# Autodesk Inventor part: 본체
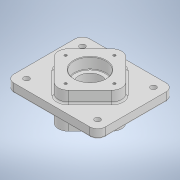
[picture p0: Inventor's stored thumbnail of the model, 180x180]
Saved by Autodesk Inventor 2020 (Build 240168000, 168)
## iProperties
Created: 2021-07
Part Number: 본체
Material: 일반
Document SubType Name: Modeling
Designer: Owner
Density: 1 g/cm^3
Appearance: 기본값
Mass: 807.973 g
Surface Area: 961.691 cm^2
Volume: 807.973 cm^3
Author: Owner
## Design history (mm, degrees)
sketch "스케치1"
  geometry: L1 (-90, 75)-(90, 75); L2 (90, 75)-(90, -75); L3 (90, -75)-(-90, -75); L4 (-90, -75)-(-90, 75); L5 (-90, 75)-(90, -75); L6 (90, 75)-(-90, -75); 1 further point
  constraints: 12 end point, 2 midpoint, 2 parallel, 1 horizontal, 1 perpendicular
  dimensions: "d0" = 150 distance of L1.end L2.end; "d1" = 180 distance of L2.end L3.end
extrude "돌출1" new body sketch "스케치1" stored distance "d2" = 18; taper "d3" = 0 deg
sketch "스케치2"
  geometry: L1 (0, -70.711)-(-70.711, 0); L2 (-70.711, 0)-(0, 70.711); L3 (0, 70.711)-(70.711, 0); L4 (70.711, 0)-(0, -70.711); 1 further point
  constraints: 8 end point, 2 parallel, 2 vertical alignment, 1 horizontal alignment, 1 perpendicular
  dimensions: "d4" = 100 distance of L1.end L2.end; "d5" = 100 distance of L2.end L3.end
extrude "돌출2" join sketch "스케치2" distance "d6" = 23; taper "d7" = 0 deg
sketch "스케치3"
  geometry: L1 (0, -70.711)-(-70.711, 0) reference; L2 (-70.711, 0)-(0, 70.711) reference; L3 (0, 70.711)-(70.711, 0) reference; L4 (70.711, 0)-(0, -70.711) reference; 1 further point
extrude "돌출3" join sketch "스케치3" distance "d8" = 29; taper "d9" = 0 deg
fillet "모깎기1" dims "d10" = 15
fillet "모깎기2" dims "d11" = 20
sketch "스케치4"
  geometry: L1 (90, -60)-(90, 60) reference; L2 (75, 75)-(-75, 75) reference; C1 r 11 at (70, 55); 1 further point
  constraints: 1 centre point
  dimensions: "d12" = 20 distance from line of L1 C1.centre; "d13" = 20 distance from line of L2 C1.centre; "d14" = 22 diameter of C1
extrude "돌출4" join sketch "스케치4" distance "d15" = 5; taper "d16" = 0 deg
sketch "스케치5"
  geometry: C1 r 11 at (0, 0) reference; C2 r 11 at (0, -110) reference; C3 r 11 at (-140, -110) reference; C4 r 11 at (-140, 0) reference; 5 further points
  constraints: 4 coincident
hole "구멍1" sketch "스케치5" at (0, 0), (0, -110), (-140, -110), (-140, 0) diameter "d23" = 11; stored, may be unused: countersink angle "d27" = 90 deg, drill point angle "d29" = 118 deg; dims "d24" = 6, "d25" = 4, "d26" = 2, "d28" = 8
sketch "스케치7"
  geometry: C1 r 31 at (0, 0); 1 further point
  constraints: 1 centre point, 1 coincident
  dimensions: "d30" = 62 diameter of C1
extrude "돌출5" cut sketch "스케치7" distance "d31" = 22; taper "d32" = 0 deg
sketch "스케치8"
  geometry: C1 r 31 at (0, 0) reference; C2 r 22.5 at (0, 0); 1 further point
  constraints: 1 centre point, 1 coincident
  dimensions: "d33" = 45 diameter of C2
extrude "돌출6" cut sketch "스케치8" distance "d34" = 26; taper "d35" = 0 deg
sketch "스케치9"
  geometry: C1 r 31 at (0, 0); 1 further point
  constraints: 1 centre point, 1 coincident
  dimensions: "d36" = 62 diameter of C1
extrude "돌출7" cut sketch "스케치9" distance "d37" = 22; taper "d38" = 0 deg
sketch "스케치10"
  geometry: 2 further points
  constraints: 1 horizontal alignment
  dimensions: "d39" = 48 distance of point (0, 0) point (48, 0)
hole "구멍2" sketch "스케치10" at (48, 0) diameter "d40" = 4.917; stored, may be unused: countersink angle "d44" = 90 deg, drill point angle "d46" = 118 deg; dims "d41" = 10, "d42" = 4, "d43" = 2, "d45" = 13
sketch "스케치11"
  geometry: 2 further points
  constraints: 1 vertical alignment
  dimensions: "d50" = 48 distance of point (0, 0) point (0, -48)
hole "구멍3" sketch "스케치11" at (0, -48) diameter "d51" = 4.917; stored, may be unused: countersink angle "d55" = 90 deg, drill point angle "d57" = 118 deg; dims "d52" = 10, "d53" = 4, "d54" = 2, "d56" = 13
fillet "모깎기3" dims "d61" = 3
fillet "모깎기4" dims "d62" = 1
chamfer "모따기1" distance "d63" = 1; stored, may be unused: second distance "d64" = 2, angle "d65" = 45 deg
sketch "스케치12"
  geometry: L1 (-90, 60)-(-90, -60) reference; 3 further points
  constraints: 1 horizontal alignment, 1 midpoint, 1 other
  dimensions: "d66" = 15 distance from line of L1 point (-75, 0)
feature "엠보싱1" sketch "스케치12" dims "d0" = 150, "d1" = 180, "d9" = 0, "d67" = 0.5, "d68" = 0
fillet "모깎기5" dims "d69" = 3
node "솔리드1"
pattern_linear "직사각형 패턴1" dims "d19" = 140, "d22" = 110
pattern_circular "원형 패턴1" dims angle "d48" = 360 deg
pattern_circular "원형 패턴2" dims angle "d59" = 360 deg
node "투영된 루프1"
feature "A9D066F2-1C7D-4E18-AEED-F7BC21143FA4" dims "d23" = 11, "d24" = 6, "d25" = 4, "d26" = 2, "d27" = 90 deg, "d28" = 8, "d29" = 118 deg
